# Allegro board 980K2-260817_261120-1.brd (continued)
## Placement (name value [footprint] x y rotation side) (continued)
NOREF#2378  -  []  268.19 247.71 0 top
NOREF#2379  -  []  216.55 194.49 90 top
NOREF#2380  -  []  138.35 209.04 0 top
NOREF#2381  -  []  260.95 261.55 90 top
NOREF#2382  -  []  277.71 233.69 90 top
NOREF#2383  -  []  269.67 250.01 0 top
NOREF#2384  -  []  248.42 205.58 0 top
NOREF#2385  -  []  136.55 254.49 90 top
NOREF#2386  -  []  268.78 244.35 0 top
NOREF#2387  -  []  192.72 257.6 0 top
NOREF#2388  -  []  220.83 203.76 90 top
NOREF#2389  -  []  148.19 187.71 0 top
NOREF#2390  -  []  232.11 231.4 0 top
NOREF#2391  -  []  118.64 291.4 0 top
NOREF#2392  -  []  176.26 203.76 90 top
NOREF#2393  -  []  196.1 220.99 90 top
NOREF#2394  -  []  228.99 180.62 0 top
NOREF#2395  -  []  122.44 232.28 0 top
NOREF#2396  -  []  230.6 233.69 0 top
NOREF#2397  -  []  155.05 274.25 0 top
NOREF#2398  -  []  265.42 214.72 90 top
NOREF#2399  -  []  252.55 284.49 0 top
NOREF#2400  -  []  188.78 222.65 0 top
NOREF#2401  -  []  197.03 178.07 0 top
NOREF#2402  -  []  203.97 265.9 0 top
NOREF#2403  -  []  191.46 167 0 top
NOREF#2404  -  []  244.95 270.32 90 top
NOREF#2405  -  []  124.44 292.28 90 top
NOREF#2406  -  []  153.18 184.35 0 top
NOREF#2407  -  []  192.25 278.02 90 top
NOREF#2408  -  []  181.03 267.69 90 top
NOREF#2409  -  []  243.97 214.54 0 top
NOREF#2410  -  []  249.52 200.42 90 top
NOREF#2411  -  []  139.72 213.6 90 top
NOREF#2412  -  []  232.63 233.69 90 top
NOREF#2413  -  []  266.43 282.49 90 top
NOREF#2414  -  []  150.21 82.65 0 top
NOREF#2415  -  []  191.98 220.75 90 top
NOREF#2416  -  []  193.18 184.35 0 top
NOREF#2417  -  []  217.25 176.5 90 top
NOREF#2418  -  []  235.92 250.88 90 top
NOREF#2419  -  []  276.1 271.85 90 top
NOREF#2420  -  []  276.57 185.63 90 top
NOREF#2421  -  []  152.13 220.09 0 top
NOREF#2422  -  []  159.27 211.67 0 top
NOREF#2423  -  []  210.89 209.17 0 top
NOREF#2424  -  []  275.49 228.7 90 top
NOREF#2425  -  []  147.77 252.5 0 top
NOREF#2426  -  []  246.32 209.17 0 top
NOREF#2427  -  []  191.46 227 0 top
NOREF#2428  -  []  286.32 202.32 0 top
NOREF#2429  -  []  148.32 245.63 90 top
NOREF#2430  -  []  143.36 258.18 0 top
NOREF#2431  -  []  279.4 214.54 0 top
NOREF#2432  -  []  176.55 220.49 0 top
NOREF#2433  -  []  237.25 196.75 0 top
NOREF#2434  -  []  199.22 239.57 90 top
NOREF#2435  -  []  321.52 456.29 0 top
NOREF#2436  -  []  271.19 278.07 0 top
NOREF#2437  -  []  281.75 266.13 0 top
NOREF#2438  -  []  273.56 233.37 90 top
NOREF#2439  -  []  163.84 273.41 90 top
NOREF#2440  -  []  190.73 19.69 90 top
NOREF#2441  -  []  222.87 273.02 0 top
NOREF#2442  -  []  227.77 241.47 0 top
NOREF#2443  -  []  251.25 244.35 0 top
NOREF#2444  -  []  202.26 176.17 90 top
NOREF#2445  -  []  275.96 228.6 90 top
NOREF#2446  -  []  236.8 274.65 90 top
NOREF#2447  -  []  197.25 196.75 0 top
NOREF#2448  -  []  272.11 231.4 0 top
NOREF#2449  -  []  170.92 291.95 90 top
NOREF#2450  -  []  196.54 227 0 top
NOREF#2451  -  []  208.54 207.5 90 top
NOREF#2452  -  []  131.22 234.24 90 top
NOREF#2453  -  []  176.55 254.49 90 top
NOREF#2454  -  []  262.87 226.99 0 top
NOREF#2455  -  []  271.95 178.07 0 top
NOREF#2456  -  []  203.97 208.95 0 top
NOREF#2457  -  []  138.97 271.91 90 top
NOREF#2458  -  []  211.25 244.35 0 top
NOREF#2459  -  []  255.02 268.14 90 top
NOREF#2460  -  []  203.97 272 0 top
NOREF#2461  -  []  163.97 208.95 0 top
NOREF#2462  -  []  236.02 192.78 0 top
NOREF#2463  -  []  267.3 286.19 0 top
NOREF#2464  -  []  162.2 178.35 0 top
NOREF#2465  -  []  253.36 201.22 0 top
NOREF#2466  -  []  159.4 205.9 0 top
NOREF#2467  -  []  148.44 193.03 90 top
NOREF#2468  -  []  181.55 269.94 90 top
NOREF#2469  -  []  181.6 294.14 0 top
NOREF#2470  -  []  230.56 197.6 0 top
NOREF#2471  -  []  272.63 232.86 0 top
NOREF#2472  -  []  175.65 244.35 0 top
NOREF#2473  -  []  228.99 251.93 0 top
NOREF#2474  -  []  180.95 261.55 90 top
NOREF#2475  -  []  232.66 166.36 90 top
NOREF#2476  -  []  109.54 14.59 90 top
NOREF#2477  -  []  168.45 235.2 0 top
NOREF#2478  -  []  279.4 274.54 0 top
NOREF#2479  -  []  154.86 454.29 90 top
NOREF#2480  -  []  151.11 253.35 0 top
NOREF#2481  -  []  253.45 184.35 0 top
NOREF#2482  -  []  193.39 197.85 90 top
NOREF#2483  -  []  163.84 214.21 0 top
NOREF#2484  -  []  193.83 172.21 90 top
NOREF#2485  -  []  239.72 219.22 90 top
NOREF#2486  -  []  259.55 294.49 0 top
NOREF#2487  -  []  228.32 198.18 0 top
NOREF#2488  -  []  189.12 256.43 90 top
NOREF#2489  -  []  134.38 264.09 0 top
NOREF#2490  -  []  133.95 281.02 90 top
NOREF#2491  -  []  180.95 208.91 90 top
NOREF#2492  -  []  178.97 18.69 90 top
NOREF#2493  -  []  187.99 178.35 0 top
NOREF#2494  -  []  196.57 185.63 0 top
NOREF#2495  -  []  246.32 266.13 0 top
NOREF#2496  -  []  205.38 226.23 0 top
NOREF#2497  -  []  186.83 256.75 0 top
NOREF#2498  -  []  153.83 172.21 90 top
NOREF#2499  -  []  89.76 165.64 0 top
NOREF#2500  -  []  273.76 255.7 90 top
NOREF#2501  -  []  196.52 285.69 0 top
NOREF#2502  -  []  275.15 236.17 90 top
NOREF#2503  -  []  269.55 188.99 90 top
NOREF#2504  -  []  195.17 281.32 0 top
NOREF#2505  -  []  271.79 196.75 0 top
NOREF#2506  -  []  171.65 293.3 90 top
NOREF#2507  -  []  195.05 214.25 0 top
NOREF#2508  -  []  290.89 262.32 0 top
NOREF#2509  -  []  235.92 190.88 90 top
NOREF#2510  -  []  250.89 266.13 0 top
NOREF#2511  -  []  156.8 220.49 90 top
NOREF#2512  -  []  163.84 270.87 90 top
NOREF#2513  -  []  256.98 205.11 90 top
NOREF#2514  -  []  139.08 203.76 0 top
NOREF#2515  -  []  192.13 224.66 0 top
NOREF#2516  -  []  210.89 269.17 0 top
NOREF#2517  -  []  236.61 233.37 90 top
NOREF#2518  -  []  149.12 196.43 90 top
NOREF#2519  -  []  133.68 389.27 90 top
NOREF#2520  -  []  258.95 261.55 0 top
NOREF#2521  -  []  251.21 294.89 90 top
NOREF#2522  -  []  151.91 196.43 90 top
NOREF#2523  -  []  132.26 248.4 0 top
NOREF#2524  -  []  229.84 213.7 0 top
NOREF#2525  -  []  282.26 236.17 90 top
NOREF#2526  -  []  231.71 171.3 0 top
NOREF#2527  -  []  182.81 257.6 0 top
NOREF#2528  -  []  218.35 211.84 0 top
NOREF#2529  -  []  225.61 257.6 0 top
NOREF#2530  -  []  220.43 284.38 90 top
NOREF#2531  -  []  248.42 204.78 90 top
NOREF#2532  -  []  149.29 276.17 90 top
NOREF#2533  -  []  242.44 232.28 0 top
NOREF#2534  -  []  216.63 292.23 0 top
NOREF#2535  -  []  236.1 211.85 90 top
NOREF#2536  -  []  275.49 168.7 90 top
NOREF#2537  -  []  174.38 204.09 0 top
NOREF#2538  -  []  248.42 261.77 0 top
NOREF#2539  -  []  226.16 200.17 90 top
NOREF#2540  -  []  236.52 221.12 0 top
NOREF#2541  -  []  288.42 208.62 0 top
NOREF#2542  -  []  251.25 244.35 0 top
NOREF#2543  -  []  152.63 172.86 0 top
NOREF#2544  -  []  138.95 208.91 0 top
NOREF#2545  -  []  239.27 260.97 90 top
NOREF#2546  -  []  214.38 264.09 0 top
NOREF#2547  -  []  237.71 173.69 0 top
NOREF#2548  -  []  198.11 232.1 0 top
NOREF#2549  -  []  279.4 200.64 90 top
NOREF#2550  -  []  203.97 260.64 90 top
NOREF#2551  -  []  243.97 200.64 90 top
NOREF#2552  -  []  164.64 241.15 90 top
NOREF#2553  -  []  168.42 261.77 0 top
NOREF#2554  -  []  205.38 286.23 0 top
NOREF#2555  -  []  168.42 268.62 0 top
NOREF#2556  -  []  267.43 278.27 90 top
NOREF#2557  -  []  271.24 193.03 90 top
NOREF#2558  -  []  198.64 173.37 90 top
NOREF#2559  -  []  199.27 201.77 0 top
NOREF#2560  -  []  187.43 218.27 90 top
NOREF#2561  -  []  258.97 211.91 90 top
NOREF#2562  -  []  191.85 18.69 0 top
NOREF#2563  -  []  250.02 274.45 0 top
NOREF#2564  -  []  239.27 271.67 0 top
NOREF#2565  -  []  226.7 283.04 90 top
NOREF#2566  -  []  278.64 173.37 90 top
NOREF#2567  -  []  128.94 265.53 0 top
NOREF#2568  -  []  156.52 216.55 0 top
NOREF#2569  -  []  269.12 240.3 90 top
NOREF#2570  -  []  146.01 195.7 90 top
NOREF#2571  -  []  265.41 213.02 90 top
NOREF#2572  -  []  260.95 204.09 90 top
NOREF#2573  -  []  199.4 208.95 0 top
NOREF#2574  -  []  286.32 206.13 0 top
NOREF#2575  -  []  106.83 148.19 90 top
NOREF#2576  -  []  283.84 264.78 90 top
NOREF#2577  -  []  163.84 264.78 90 top
NOREF#2578  -  []  248.94 221.73 0 top
NOREF#2579  -  []  276.57 185.63 0 top
NOREF#2580  -  []  214.38 204.09 0 top
NOREF#2581  -  []  188.44 193.03 90 top
NOREF#2582  -  []  244.44 292.28 90 top
NOREF#2583  -  []  267.77 241.47 0 top
NOREF#2584  -  []  263.49 193.03 90 top
NOREF#2585  -  []  191.73 232.54 0 top
NOREF#2586  -  []  271.73 232.54 0 top
NOREF#2587  -  []  196.1 271.85 90 top
NOREF#2588  -  []  151.76 227.33 0 top
NOREF#2589  -  []  163.97 200.64 90 top
NOREF#2590  -  []  125.04 233.3 90 top
NOREF#2591  -  []  119.46 18.69 90 top
NOREF#2592  -  []  226.96 251.6 90 top
NOREF#2593  -  []  279.72 274.65 90 top
NOREF#2594  -  []  219.55 294.49 0 top
NOREF#2595  -  []  199.27 214.21 0 top
NOREF#2596  -  []  199.65 272.56 0 top
NOREF#2597  -  []  229.84 284.11 90 top
NOREF#2598  -  []  276.8 214.65 90 top
NOREF#2599  -  []  149.84 273.7 0 top
NOREF#2600  -  []  191.98 280.75 90 top
NOREF#2601  -  []  135.24 201.55 90 top
NOREF#2602  -  []  252.64 204.47 0 top
NOREF#2603  -  []  263.36 253.35 0 top
NOREF#2604  -  []  226.83 191.93 0 top
NOREF#2605  -  []  243.84 200.97 90 top
NOREF#2606  -  []  226.16 260.17 90 top
NOREF#2607  -  []  196.8 285.06 90 top
NOREF#2608  -  []  224.04 256.75 0 top
NOREF#2609  -  []  193.95 256.75 0 top
NOREF#2610  -  []  147.03 171.4 0 top
NOREF#2611  -  []  136.5 285.91 90 top
NOREF#2612  -  []  243.97 265.9 0 top
NOREF#2613  -  []  180.95 268.91 90 top
NOREF#2614  -  []  201.75 212.22 0 top
NOREF#2615  -  []  191.91 191.6 90 top
NOREF#2616  -  []  267.43 224.11 90 top
NOREF#2617  -  []  276.57 258.18 0 top
NOREF#2618  -  []  199.72 283.79 90 top
NOREF#2619  -  []  142.88 286.99 0 top
NOREF#2620  -  []  283.84 205.58 0 top
NOREF#2621  -  []  145.61 192.78 0 top
NOREF#2622  -  []  234.78 236.5 90 top
NOREF#2623  -  []  223.49 247.06 90 top
NOREF#2624  -  []  196.45 247.71 0 top
NOREF#2625  -  []  218.83 292.23 0 top
NOREF#2626  -  []  149.21 17.15 90 top
NOREF#2627  -  []  262.81 252.78 0 top
NOREF#2628  -  []  192.25 212.18 0 top
NOREF#2629  -  []  188.81 250.88 90 top
NOREF#2630  -  []  140.83 203.76 90 top
NOREF#2631  -  []  269.24 185.31 90 top
NOREF#2632  -  []  230.15 206.89 90 top
NOREF#2633  -  []  203.92 289.94 0 top
NOREF#2634  -  []  229.84 273.7 90 top
NOREF#2635  -  []  276.1 220.99 90 top
NOREF#2636  -  []  191.91 256.43 90 top
NOREF#2637  -  []  155.05 218.82 0 top
NOREF#2638  -  []  168.54 265.9 0 top
NOREF#2639  -  []  279.27 270.87 90 top
NOREF#2640  -  []  153.83 232.21 90 top
NOREF#2641  -  []  138.85 181.15 90 top
NOREF#2642  -  []  189.55 248.99 90 top
NOREF#2643  -  []  208.42 207.82 90 top
NOREF#2644  -  []  277.04 184.35 0 top
NOREF#2645  -  []  249.52 260.42 90 top
NOREF#2646  -  []  151.11 200.17 90 top
NOREF#2647  -  []  187.45 209.24 0 top
NOREF#2648  -  []  147.9 265.84 90 top
NOREF#2649  -  []  232.13 284.66 0 top
NOREF#2650  -  []  223.49 193.03 90 top
NOREF#2651  -  []  136.5 271.94 0 top
NOREF#2652  -  []  193.03 232.1 0 top
NOREF#2653  -  []  183.49 247.06 90 top
NOREF#2654  -  []  276.8 285.06 90 top
NOREF#2655  -  []  275.68 173.69 90 top
NOREF#2656  -  []  273.94 196.75 0 top
NOREF#2657  -  []  199.27 210.87 90 top
NOREF#2658  -  []  284.95 210.32 90 top
NOREF#2659  -  []  266.01 184.91 90 top
NOREF#2660  -  []  243.92 289.94 0 top
NOREF#2661  -  []  154.39 222.02 90 top
NOREF#2662  -  []  197.5 185.31 90 top
NOREF#2663  -  []  148.35 217.95 90 top
NOREF#2664  -  []  259.08 263.76 0 top
NOREF#2665  -  []  220.83 201.22 90 top
NOREF#2666  -  []  142.81 252.5 0 top
NOREF#2667  -  []  197.37 196.43 90 top
NOREF#2668  -  []  169.52 270.32 90 top
NOREF#2669  -  []  269.86 17.15 0 top
NOREF#2670  -  []  220.83 263.76 90 top
NOREF#2671  -  []  242.2 238.35 0 top
NOREF#2672  -  []  272.63 172.86 0 top
NOREF#2673  -  []  191.87 396.29 0 top
NOREF#2674  -  []  248.54 265.9 0 top
NOREF#2675  -  []  226.43 236.47 90 top
NOREF#2676  -  []  203.84 270.87 90 top
NOREF#2677  -  []  221.85 232.5 0 top
NOREF#2678  -  []  187.03 171.4 0 top
NOREF#2679  -  []  244.61 294.24 90 top
NOREF#2680  -  []  229.12 191.6 90 top
NOREF#2681  -  []  275.05 283.39 0 top
NOREF#2682  -  []  220.43 224.38 90 top
NOREF#2683  -  []  237.71 232.86 0 top
NOREF#2684  -  []  208.42 204.78 90 top
NOREF#2685  -  []  235.92 255.7 90 top
NOREF#2686  -  []  266.28 197.85 90 top
NOREF#2687  -  []  246.32 212.22 0 top
NOREF#2688  -  []  234.78 176.5 90 top
NOREF#2689  -  []  199.24 184.35 0 top
NOREF#2690  -  []  181.22 76.69 90 top
NOREF#2691  -  []  198.64 233.37 90 top
NOREF#2692  -  []  267.8 269.99 0 top
NOREF#2693  -  []  244.95 272.86 90 top
NOREF#2694  -  []  169.52 267.27 90 top
NOREF#2695  -  []  133.4 281.8 90 top
NOREF#2696  -  []  157.37 240.3 90 top
NOREF#2697  -  []  215.02 268.14 90 top
NOREF#2698  -  []  196.8 280.49 90 top
NOREF#2699  -  []  264.16 185.63 90 top
NOREF#2700  -  []  275.17 276.75 90 top
NOREF#2701  -  []  163.97 268.95 0 top
NOREF#2702  -  []  211.25 184.35 0 top
NOREF#2703  -  []  281.75 272.22 0 top
NOREF#2704  -  []  243.97 208.95 0 top
NOREF#2705  -  []  179.55 234.49 0 top
NOREF#2706  -  []  213.65 179.15 0 top
NOREF#2707  -  []  281.75 269.17 0 top
NOREF#2708  -  []  152.13 280.09 0 top
NOREF#2709  -  []  132.55 250.49 90 top
NOREF#2710  -  []  270.97 255.7 90 top
NOREF#2711  -  []  226.16 286.14 90 top
NOREF#2712  -  []  157.71 233.69 0 top
NOREF#2713  -  []  267.3 226.19 0 top
NOREF#2714  -  []  204.95 212.86 90 top
NOREF#2715  -  []  271.71 231.3 0 top
NOREF#2716  -  []  267.8 209.99 0 top
NOREF#2717  -  []  269.84 219.54 90 top
NOREF#2718  -  []  213.75 452.29 90 top
NOREF#2719  -  []  122.44 292.28 0 top
NOREF#2720  -  []  151.73 232.54 0 top
NOREF#2721  -  []  284.95 267.27 90 top
NOREF#2722  -  []  277.04 184.35 0 top
NOREF#2723  -  []  270.97 239.57 90 top
NOREF#2724  -  []  155.17 216.75 0 top
NOREF#2725  -  []  267.43 218.27 90 top
NOREF#2726  -  []  239.22 190.88 90 top
NOREF#2727  -  []  215.02 208.14 90 top
NOREF#2728  -  []  271.91 191.6 90 top
NOREF#2729  -  []  232.25 278.02 0 top
NOREF#2730  -  []  196.1 216.42 90 top
NOREF#2731  -  []  135.15 265.24 0 top
NOREF#2732  -  []  152.13 224.66 0 top
NOREF#2733  -  []  212.55 284.49 0 top
NOREF#2734  -  []  180.95 264.09 90 top
NOREF#2735  -  []  163.84 261.77 0 top
NOREF#2736  -  []  127.98 226.38 90 top
NOREF#2737  -  []  199.27 205.58 0 top
NOREF#2738  -  []  265.41 273.02 90 top
NOREF#2739  -  []  196.52 276.55 0 top
NOREF#2740  -  []  146.17 272.17 90 top
NOREF#2741  -  []  267.8 204.99 90 top
NOREF#2742  -  []  143.61 456.29 0 top
NOREF#2743  -  []  268.99 240.62 0 top
NOREF#2744  -  []  171.25 244.35 0 top
NOREF#2745  -  []  290.89 206.13 0 top
NOREF#2746  -  []  192.66 226.35 90 top
NOREF#2747  -  []  192.13 280.09 0 top
NOREF#2748  -  []  272.25 218.02 90 top
NOREF#2749  -  []  275.05 223.39 0 top
NOREF#2750  -  []  245.38 286.23 0 top
NOREF#2751  -  []  166.32 206.13 0 top
NOREF#2752  -  []  253.45 244.35 0 top
NOREF#2753  -  []  259.08 208.59 0 top
NOREF#2754  -  []  186.16 258.18 0 top
NOREF#2755  -  []  170.89 202.32 0 top
NOREF#2756  -  []  253.36 261.22 0 top
NOREF#2757  -  []  149.55 156.49 90 top
NOREF#2758  -  []  136.26 203.76 90 top
NOREF#2759  -  []  159.27 267.82 90 top
NOREF#2760  -  []  186.16 200.17 90 top
NOREF#2761  -  []  192.25 282.59 0 top
NOREF#2762  -  []  205.04 233.3 90 top
NOREF#2763  -  []  196.84 227.33 0 top
NOREF#2764  -  []  239.27 210.87 90 top
NOREF#2765  -  []  279.27 260.97 90 top
NOREF#2766  -  []  271.19 218.07 0 top
NOREF#2767  -  []  178.95 268.91 0 top
NOREF#2768  -  []  173.36 261.22 0 top
NOREF#2769  -  []  223.36 247.38 0 top
NOREF#2770  -  []  152.66 166.36 90 top
NOREF#2771  -  []  229.72 281.62 0 top
NOREF#2772  -  []  131.22 294.89 90 top
NOREF#2773  -  []  191.18 179.15 0 top
NOREF#2774  -  []  251.25 184.35 0 top
NOREF#2775  -  []  133.66 179.15 0 top
NOREF#2776  -  []  88.16 165.19 0 top
NOREF#2777  -  []  155.92 190.88 90 top
NOREF#2778  -  []  183.36 253.35 0 top
NOREF#2779  -  []  233.18 271.85 90 top
NOREF#2780  -  []  86.61 153.16 0 top
NOREF#2781  -  []  269.84 284.11 0 top
NOREF#2782  -  []  278.91 172.21 90 top
NOREF#2783  -  []  174.09 267.27 90 top
NOREF#2784  -  []  179.55 180.49 90 top
NOREF#2785  -  []  159.27 265.58 0 top
NOREF#2786  -  []  195.92 255.7 90 top
NOREF#2787  -  []  230.48 175.77 0 top
NOREF#2788  -  []  277.74 166.36 90 top
NOREF#2789  -  []  276.38 181.15 90 top
NOREF#2790  -  []  231.76 227.33 0 top
NOREF#2791  -  []  163.84 201.77 0 top
NOREF#2792  -  []  224.16 245.63 90 top
NOREF#2793  -  []  241.12 248.11 90 top
NOREF#2794  -  []  213.65 239.15 0 top
NOREF#2795  -  []  139.55 234.49 0 top
NOREF#2796  -  []  200.23 176.17 90 top
NOREF#2797  -  []  170.89 209.17 0 top
NOREF#2798  -  []  234.39 216.17 90 top
NOREF#2799  -  []  155.17 272.17 0 top
NOREF#2800  -  []  151.95 238.07 0 top
NOREF#2801  -  []  260.83 205.79 90 top
NOREF#2802  -  []  253.78 207.01 0 top
NOREF#2803  -  []  227.8 204.99 90 top
NOREF#2804  -  []  226.96 256.43 90 top
NOREF#2805  -  []  201.12 188.11 90 top
NOREF#2806  -  []  258.95 268.91 0 top
NOREF#2807  -  []  182.81 252.78 0 top
NOREF#2808  -  []  165.04 233.3 90 top
NOREF#2809  -  []  235.68 173.69 0 top
NOREF#2810  -  []  209.52 270.32 90 top
NOREF#2811  -  []  138.35 204.47 0 top
NOREF#2812  -  []  156.02 236.37 0 top
NOREF#2813  -  []  197.74 226.35 90 top
NOREF#2814  -  []  230.56 252.78 0 top
NOREF#2815  -  []  269.72 221.62 0 top
NOREF#2816  -  []  278.11 172.1 0 top
NOREF#2817  -  []  221.59 308.11 0 top
NOREF#2818  -  []  167.98 286.38 90 top
NOREF#2819  -  []  279.4 207.5 90 top
NOREF#2820  -  []  227.45 209.24 0 top
NOREF#2821  -  []  227.3 280.35 0 top
NOREF#2822  -  []  151.91 251.6 90 top
NOREF#2823  -  []  209.55 237.49 90 top
NOREF#2824  -  []  279.4 273.09 90 top
NOREF#2825  -  []  307.66 457.2 0 top
NOREF#2826  -  []  251.05 289.49 0 top
NOREF#2827  -  []  152.25 278.02 90 top
NOREF#2828  -  []  203.97 273.09 90 top
NOREF#2829  -  []  183.36 187.38 0 top
NOREF#2830  -  []  184.16 256.43 90 top
NOREF#2831  -  []  208.42 200.97 90 top
NOREF#2832  -  []  152.72 197.6 0 top
NOREF#2833  -  []  276.52 276.55 0 top
NOREF#2834  -  []  85.59 155.57 90 top
NOREF#2835  -  []  228.32 185.63 0 top
NOREF#2836  -  []  124.32 231.95 90 top
NOREF#2837  -  []  181.55 205.11 90 top
NOREF#2838  -  []  156.81 172.54 0 top
NOREF#2839  -  []  208.42 201.77 0 top
NOREF#2840  -  []  227.03 171.4 0 top
NOREF#2841  -  []  267.99 178.35 0 top
NOREF#2842  -  []  213.62 229.09 90 top
NOREF#2843  -  []  236.33 227.9 90 top
NOREF#2844  -  []  224.04 196.75 0 top
NOREF#2845  -  []  199.27 273.41 90 top
NOREF#2846  -  []  212.87 287.4 90 top
NOREF#2847  -  []  216.26 263.76 90 top
NOREF#2848  -  []  258.35 207.01 0 top
NOREF#2849  -  []  157.92 252.5 90 top
NOREF#2850  -  []  216.63 232.23 0 top
NOREF#2851  -  []  132.87 287.4 90 top
NOREF#2852  -  []  245.73 17.15 0 top
NOREF#2853  -  []  188.44 181.72 90 top
NOREF#2854  -  []  161.75 214.76 0 top
NOREF#2855  -  []  148.35 223.79 90 top
NOREF#2856  -  []  219.08 261.22 0 top
NOREF#2857  -  []  270.48 235.77 0 top
NOREF#2858  -  []  138.35 211.84 0 top
NOREF#2859  -  []  275.92 195.7 90 top
NOREF#2860  -  []  147.99 178.35 0 top
NOREF#2861  -  []  203.84 261.77 0 top
NOREF#2862  -  []  154.51 259.27 90 top
NOREF#2863  -  []  207.98 286.38 90 top
NOREF#2864  -  []  123.92 229.94 0 top
NOREF#2865  -  []  271.19 283.92 0 top
NOREF#2866  -  []  288.54 262.09 0 top
NOREF#2867  -  []  231.98 226.59 90 top
NOREF#2868  -  []  262.87 286.99 0 top
NOREF#2869  -  []  227.99 178.35 0 top
NOREF#2870  -  []  248.54 202.09 0 top
NOREF#2871  -  []  227.99 238.35 0 top
NOREF#2872  -  []  159.27 271.67 0 top
NOREF#2873  -  []  254.07 270.89 90 top
NOREF#2874  -  []  287.25 19.69 90 top
NOREF#2875  -  []  273.18 222.26 90 top
NOREF#2876  -  []  267.8 264.99 90 top
NOREF#2877  -  []  212.55 250.49 90 top
NOREF#2878  -  []  226.28 253.03 90 top
NOREF#2879  -  []  157.71 173.69 90 top
NOREF#2880  -  []  236.1 280.99 90 top
NOREF#2881  -  []  191.79 191.93 0 top
NOREF#2882  -  []  261.55 265.11 90 top
NOREF#2883  -  []  243.97 267.5 90 top
NOREF#2884  -  []  235.17 272.17 90 top
NOREF#2885  -  []  230.77 273.37 90 top
NOREF#2886  -  []  256.63 292.23 0 top
NOREF#2887  -  []  267.43 284.11 0 top
NOREF#2888  -  []  288.39 456.29 0 top
NOREF#2889  -  []  260.59 184.98 90 top
NOREF#2890  -  []  269.12 256.43 90 top
NOREF#2891  -  []  193.98 178.07 0 top
NOREF#2892  -  []  203.97 262.09 0 top
NOREF#2893  -  []  267.43 278.27 0 top
NOREF#2894  -  []  142.81 192.78 0 top
NOREF#2895  -  []  239.06 178.07 0 top
NOREF#2896  -  []  251.21 294.24 90 top
NOREF#2897  -  []  169.52 204.23 90 top
NOREF#2898  -  []  283.84 204.78 90 top
NOREF#2899  -  []  136.55 220.49 0 top
NOREF#2900  -  []  159.4 208.95 0 top
NOREF#2901  -  []  244.95 212.86 90 top
NOREF#2902  -  []  228.78 184.35 0 top
NOREF#2903  -  []  158.64 173.37 90 top
NOREF#2904  -  []  211.21 234.24 90 top
NOREF#2905  -  []  181.6 248.12 0 top
NOREF#2906  -  []  302.59 389.27 90 top
NOREF#2907  -  []  175.84 262.57 90 top
NOREF#2908  -  []  145.09 257.49 90 top
NOREF#2909  -  []  278.13 389.27 90 top
NOREF#2910  -  []  134.51 203.76 0 top
NOREF#2911  -  []  220.95 268.91 90 top
NOREF#2912  -  []  262.81 246.81 0 top
NOREF#2913  -  []  154.07 191.6 90 top
NOREF#2914  -  []  236.54 167 0 top
NOREF#2915  -  []  221.55 262.57 90 top
NOREF#2916  -  []  168.42 267.82 90 top
NOREF#2917  -  []  83.04 164.54 90 top
NOREF#2918  -  []  169.49 220.89 0 top
NOREF#2919  -  []  170.92 231.95 90 top
NOREF#2920  -  []  227.9 265.84 90 top
NOREF#2921  -  []  133.24 201.55 0 top
NOREF#2922  -  []  265.42 274.72 90 top
NOREF#2923  -  []  192.25 222.59 0 top
NOREF#2924  -  []  228.95 206.89 0 top
NOREF#2925  -  []  269.72 286.19 0 top
NOREF#2926  -  []  270.6 233.69 0 top
NOREF#2927  -  []  209.55 237.49 90 top
NOREF#2928  -  []  221.6 17.15 90 top
NOREF#2929  -  []  268.32 242.05 0 top
NOREF#2930  -  []  195.92 250.88 90 top
NOREF#2931  -  []  154.63 277.85 0 top
NOREF#2932  -  []  195.49 228.7 90 top
NOREF#2933  -  []  184.16 251.6 90 top
NOREF#2934  -  []  229.84 219.54 0 top
NOREF#2935  -  []  273.6 282.39 0 top
NOREF#2936  -  []  264.04 245.96 0 top
NOREF#2937  -  []  199.27 270.87 90 top
NOREF#2938  -  []  178.35 264.47 0 top
NOREF#2939  -  []  235.17 216.75 0 top
NOREF#2940  -  []  266.96 251.6 90 top
NOREF#2941  -  []  196.57 242.05 0 top
NOREF#2942  -  []  137.25 176.5 90 top
NOREF#2943  -  []  231.19 288.49 0 top
NOREF#2944  -  []  181.85 246.47 0 top
NOREF#2945  -  []  146.16 258.18 0 top
NOREF#2946  -  []  279.72 279.22 90 top
NOREF#2947  -  []  159.27 274.21 0 top
NOREF#2948  -  []  236.79 171.3 0 top
NOREF#2949  -  []  237.92 190.01 0 top
NOREF#2950  -  []  245.38 286.23 0 top
NOREF#2951  -  []  231.95 178.07 0 top
NOREF#2952  -  []  233.39 253.03 90 top
NOREF#2953  -  []  187.77 241.47 0 top
NOREF#2954  -  []  195.49 168.7 90 top
NOREF#2955  -  []  279.4 264.45 90 top
NOREF#2956  -  []  231.11 193.35 0 top
NOREF#2957  -  []  154.33 207.37 90 top
NOREF#2958  -  []  318.12 17.15 90 top
NOREF#2959  -  []  216.55 254.49 90 top
NOREF#2960  -  []  231.79 191.93 0 top
NOREF#2961  -  []  248.54 267.5 90 top
NOREF#2962  -  []  277.04 244.35 0 top
NOREF#2963  -  []  288.54 204.45 90 top
NOREF#2964  -  []  207.98 226.38 90 top
NOREF#2965  -  []  212.55 224.49 0 top
NOREF#2966  -  []  236.57 245.63 90 top
NOREF#2967  -  []  144.16 251.6 90 top
NOREF#2968  -  []  226.01 250.88 90 top
NOREF#2969  -  []  174.51 263.76 0 top
NOREF#2970  -  []  159.27 260.97 90 top
NOREF#2971  -  []  276.02 257.6 0 top
NOREF#2972  -  []  275.17 221.32 0 top
NOREF#2973  -  []  222.87 213.02 0 top
NOREF#2974  -  []  264.04 256.75 0 top
NOREF#2975  -  []  209.55 237.49 90 top
NOREF#2976  -  []  229.24 185.31 90 top
NOREF#2977  -  []  259.73 178.35 0 top
NOREF#2978  -  []  229.72 286.19 0 top
NOREF#2979  -  []  183.36 198.18 0 top
NOREF#2980  -  []  148.99 191.93 0 top
NOREF#2981  -  []  159.4 214.54 0 top
NOREF#2982  -  []  132.55 284.49 0 top
NOREF#2983  -  []  184.04 245.96 0 top
NOREF#2984  -  []  263.49 247.06 90 top
NOREF#2985  -  []  239.22 239.57 90 top
NOREF#2986  -  []  174.07 270.89 90 top
NOREF#2987  -  []  188.35 223.79 90 top
NOREF#2988  -  []  272.13 280.09 0 top
NOREF#2989  -  []  235.05 223.39 0 top
NOREF#2990  -  []  270.86 82.65 0 top
NOREF#2991  -  []  197.74 166.36 90 top
NOREF#2992  -  []  125.25 291.4 0 top
NOREF#2993  -  []  209.87 389.27 90 top
NOREF#2994  -  []  169.05 232.28 0 top
NOREF#2995  -  []  165.49 452.29 90 top
NOREF#2996  -  []  149.67 252.5 90 top
NOREF#2997  -  []  239.27 261.77 0 top
NOREF#2998  -  []  233.39 197.85 90 top
NOREF#2999  -  []  264.24 18.69 0 top
NOREF#3000  -  []  179.08 261.22 0 top
NOREF#3001  -  []  141.85 246.47 0 top
NOREF#3002  -  []  203.84 213.41 90 top
NOREF#3003  -  []  289.52 204.23 90 top
NOREF#3004  -  []  260.83 268.59 90 top
NOREF#3005  -  []  235.05 214.25 0 top
NOREF#3006  -  []  275.17 212.18 90 top
NOREF#3007  -  []  208.42 268.62 0 top
NOREF#3008  -  []  130.52 295.42 90 top
NOREF#3009  -  []  162.2 238.35 0 top
NOREF#3010  -  []  288.39 456.29 90 top
NOREF#3011  -  []  195.17 221.32 90 top
NOREF#3012  -  []  277.25 191.93 0 top
NOREF#3013  -  []  250.92 291.95 90 top
NOREF#3014  -  []  279.4 202.09 0 top
NOREF#3015  -  []  146.17 286.14 90 top
NOREF#3016  -  []  196.02 252.78 0 top
NOREF#3017  -  []  148.32 245.63 0 top
NOREF#3018  -  []  248.42 200.97 90 top
NOREF#3019  -  []  144.04 191.93 0 top
NOREF#3020  -  []  253.62 289.09 90 top
NOREF#3021  -  []  236.02 252.78 0 top
NOREF#3022  -  []  89.74 155.92 0 top
NOREF#3023  -  []  279.27 271.67 0 top
NOREF#3024  -  []  267.43 218.27 0 top
NOREF#3025  -  []  203.84 267.82 90 top
NOREF#3026  -  []  205.74 14.59 90 top
NOREF#3027  -  []  272.72 257.6 0 top
NOREF#3028  -  []  152.11 231.4 0 top
NOREF#3029  -  []  146.96 191.6 90 top
NOREF#3030  -  []  206.32 269.17 0 top
NOREF#3031  -  []  208.94 281.73 0 top
NOREF#3032  -  []  267.03 231.4 0 top
NOREF#3033  -  []  203.92 229.94 0 top
NOREF#3034  -  []  269.72 275.77 0 top
NOREF#3035  -  []  243.97 204.45 90 top
NOREF#3036  -  []  221.55 265.11 90 top
NOREF#3037  -  []  227.3 286.19 0 top
NOREF#3038  -  []  247.04 299.09 0 top
NOREF#3039  -  []  163.97 272 0 top
NOREF#3040  -  []  272.87 248.11 90 top
NOREF#3041  -  []  133.64 239.09 0 top
NOREF#3042  -  []  283.97 208.95 0 top
NOREF#3043  -  []  203.97 210.55 90 top
NOREF#3044  -  []  191.11 258.18 0 top
NOREF#3045  -  []  143.49 187.06 90 top
NOREF#3046  -  []  249.52 204.23 90 top
NOREF#3047  -  []  169.05 292.28 0 top
NOREF#3048  -  []  148.44 181.72 90 top
NOREF#3049  -  []  166.32 266.13 0 top
NOREF#3050  -  []  239.4 205.9 0 top
NOREF#3051  -  []  178.35 204.47 0 top
NOREF#3052  -  []  185.41 286.99 90 top
NOREF#3053  -  []  261.55 209.94 90 top
NOREF#3054  -  []  203.97 200.64 90 top
NOREF#3055  -  []  241.75 206.13 0 top
NOREF#3056  -  []  274.33 207.37 90 top
NOREF#3057  -  []  272.13 214.25 0 top
NOREF#3058  -  []  277.92 250.01 0 top
NOREF#3059  -  []  266.28 253.03 90 top
NOREF#3060  -  []  239.27 204.78 90 top
NOREF#3061  -  []  209.52 272.86 90 top
NOREF#3062  -  []  244.95 267.27 90 top
NOREF#3063  -  []  272.25 272.17 0 top
NOREF#3064  -  []  229.67 190.01 0 top
NOREF#3065  -  []  216.26 203.76 90 top
NOREF#3066  -  []  148.78 184.35 0 top
NOREF#3067  -  []  211.14 458.49 0 top
NOREF#3068  -  []  267.43 224.11 0 top
NOREF#3069  -  []  151.11 198.18 0 top
NOREF#3070  -  []  237.25 180.62 0 top
NOREF#3071  -  []  140.95 201.55 90 top
NOREF#3072  -  []  208.54 208.95 0 top
NOREF#3073  -  []  187.77 181.47 0 top
NOREF#3074  -  []  174.43 292.23 0 top
NOREF#3075  -  []  197.37 180.3 90 top
NOREF#3076  -  []  155.68 173.69 0 top
NOREF#3077  -  []  203.97 268.95 0 top
NOREF#3078  -  []  153.18 211.85 90 top
NOREF#3079  -  []  273.39 253.03 90 top
NOREF#3080  -  []  183.49 193.03 90 top
NOREF#3081  -  []  137.28 286.47 0 top
NOREF#3082  -  []  172.55 284.49 0 top
NOREF#3083  -  []  224.16 251.6 90 top
NOREF#3084  -  []  131.26 184.35 0 top
NOREF#3085  -  []  131.05 245.49 90 top
NOREF#3086  -  []  193.18 211.85 90 top
NOREF#3087  -  []  227.77 192.78 0 top
NOREF#3088  -  []  150.56 197.6 0 top
NOREF#3089  -  []  173.24 201.55 0 top
NOREF#3090  -  []  236.38 241.15 90 top
NOREF#3091  -  []  173.62 229.09 90 top
NOREF#3092  -  []  265.09 197.49 90 top
NOREF#3093  -  []  236.57 253.35 0 top
NOREF#3094  -  []  213.36 261.22 0 top
NOREF#3095  -  []  264.04 251.93 0 top
NOREF#3096  -  []  248.42 201.77 0 top
NOREF#3097  -  []  260.83 208.59 90 top
NOREF#3098  -  []  146.83 196.75 0 top
NOREF#3099  -  []  276.33 227.9 90 top
NOREF#3100  -  []  228.78 228.49 0 top
NOREF#3101  -  []  184.16 245.63 90 top
NOREF#3102  -  []  279.22 255.7 90 top
NOREF#3103  -  []  271.79 256.75 0 top
NOREF#3104  -  []  243.84 207.82 90 top
NOREF#3105  -  []  235.05 218.82 0 top
NOREF#3106  -  []  270.77 283.79 90 top
NOREF#3107  -  []  288.54 205.9 0 top
NOREF#3108  -  []  226.83 196.75 0 top
NOREF#3109  -  []  188.78 228.49 0 top
NOREF#3110  -  []  271.11 258.18 0 top
NOREF#3111  -  []  169.17 291.95 0 top
NOREF#3112  -  []  144.16 245.63 90 top
NOREF#3113  -  []  264.04 185.96 0 top
NOREF#3114  -  []  149.68 334.65 0 top
NOREF#3115  -  []  188.32 245.63 90 top
NOREF#3116  -  []  187.3 220.35 0 top
NOREF#3117  -  []  218.35 267.01 0 top
NOREF#3118  -  []  153.6 222.39 0 top
NOREF#3119  -  []  231.24 197.85 90 top
NOREF#3120  -  []  192.11 171.4 0 top
NOREF#3121  -  []  210.92 291.95 90 top
NOREF#3122  -  []  220.59 184.98 90 top
NOREF#3123  -  []  228.32 253.35 0 top
NOREF#3124  -  []  213.24 261.55 0 top
NOREF#3125  -  []  258.35 269.04 0 top
NOREF#3126  -  []  251.05 229.49 0 top
NOREF#3127  -  []  230.56 257.6 0 top
NOREF#3128  -  []  230.97 239.57 90 top
NOREF#3129  -  []  204.64 181.15 90 top
NOREF#3130  -  []  240.13 456.29 90 top
NOREF#3131  -  []  276.02 192.78 0 top
NOREF#3132  -  []  94.87 108.59 0 top
NOREF#3133  -  []  163.84 210.87 90 top
NOREF#3134  -  []  266.69 223.05 90 top
NOREF#3135  -  []  218.95 204.09 0 top
NOREF#3136  -  []  202.44 292.28 0 top
NOREF#3137  -  []  233.76 255.7 90 top
NOREF#3138  -  []  196.61 173.37 90 top
NOREF#3139  -  []  156.02 192.78 0 top
NOREF#3140  -  []  239.4 262.09 0 top
NOREF#3141  -  []  248.54 262.09 0 top
NOREF#3142  -  []  204.95 200.42 90 top
NOREF#3143  -  []  223.36 193.35 0 top
NOREF#3144  -  []  231.95 238.07 0 top
NOREF#3145  -  []  213.45 244.35 0 top
NOREF#3146  -  []  277.5 185.31 90 top
NOREF#3147  -  []  246.32 262.32 0 top
NOREF#3148  -  []  176.83 227.03 0 top
NOREF#3149  -  []  225.41 226.99 90 top
NOREF#3150  -  []  199.4 267.5 90 top
NOREF#3151  -  []  209.55 237.49 0 top
NOREF#3152  -  []  263.49 253.03 90 top
NOREF#3153  -  []  260.43 224.38 90 top
NOREF#3154  -  []  249.49 280.89 0 top
NOREF#3155  -  []  195.05 218.82 0 top
NOREF#3156  -  []  181.55 202.57 90 top
NOREF#3157  -  []  263.36 198.18 0 top
NOREF#3158  -  []  266.43 236.47 90 top
NOREF#3159  -  []  204.44 292.28 90 top
NOREF#3160  -  []  186.96 256.43 90 top
NOREF#3161  -  []  201.12 248.11 90 top
NOREF#3162  -  []  186.83 191.93 0 top
NOREF#3163  -  []  199.72 279.22 90 top
NOREF#3164  -  []  196.84 167.33 0 top
NOREF#3165  -  []  275.17 216.75 90 top
NOREF#3166  -  []  172.37 392.33 90 top
NOREF#3167  -  []  276.81 232.54 0 top
NOREF#3168  -  []  254.51 263.76 0 top
NOREF#3169  -  []  244.64 181.15 90 top
NOREF#3170  -  []  157.92 236.37 90 top
NOREF#3171  -  []  231.19 228.49 0 top
NOREF#3172  -  []  230.77 213.37 90 top
NOREF#3173  -  []  164.32 231.95 90 top
NOREF#3174  -  []  199.22 250.88 90 top
NOREF#3175  -  []  244.95 200.42 90 top
NOREF#3176  -  []  201.75 262.32 0 top
NOREF#3177  -  []  269.72 226.19 0 top
NOREF#3178  -  []  88.44 105.03 90 top
NOREF#3179  -  []  259.55 234.49 0 top
NOREF#3180  -  []  230.6 173.69 90 top
NOREF#3181  -  []  152.61 456.29 0 top
NOREF#3182  -  []  283.84 208.62 0 top
NOREF#3183  -  []  235.17 281.32 0 top
NOREF#3184  -  []  228.78 282.65 0 top
NOREF#3185  -  []  170.89 266.13 0 top
NOREF#3186  -  []  288.42 207.82 90 top
NOREF#3187  -  []  167.74 456.29 90 top
NOREF#3188  -  []  161.75 269.17 0 top
NOREF#3189  -  []  149.12 240.3 90 top
NOREF#3190  -  []  88.44 106.3 90 top
NOREF#3191  -  []  135.15 263.21 90 top
NOREF#3192  -  []  85.59 135.25 90 top
NOREF#3193  -  []  146.01 184.91 90 top
NOREF#3194  -  []  190.97 239.57 90 top
NOREF#3195  -  []  235.92 195.7 90 top
NOREF#3196  -  []  215.84 262.57 90 top
NOREF#3197  -  []  168.42 260.97 90 top
NOREF#3198  -  []  196.57 185.63 90 top
NOREF#3199  -  []  150.77 223.79 90 top
NOREF#3200  -  []  199.44 239.15 0 top
NOREF#3201  -  []  230.97 250.88 90 top
NOREF#3202  -  []  243.84 210.87 90 top
NOREF#3203  -  []  273.18 277.69 90 top
NOREF#3204  -  []  191.11 260.17 90 top
NOREF#3205  -  []  208.54 265.9 0 top
NOREF#3206  -  []  283.97 260.64 90 top
NOREF#3207  -  []  166.32 272.22 0 top
NOREF#3208  -  []  144.16 185.63 90 top
NOREF#3209  -  []  193.27 193.35 0 top
NOREF#3210  -  []  190.98 244.35 0 top
NOREF#3211  -  []  199.72 214.65 90 top
NOREF#3212  -  []  183.49 187.06 90 top
NOREF#3213  -  []  253.24 261.55 0 top
NOREF#3214  -  []  222.81 192.78 0 top
NOREF#3215  -  []  243.84 274.21 0 top
NOREF#3216  -  []  276.79 231.3 0 top
NOREF#3217  -  []  271.18 179.15 0 top
NOREF#3218  -  []  156.1 220.99 90 top
NOREF#3219  -  []  189.72 281.62 0 top
NOREF#3220  -  []  249.52 207.27 90 top
NOREF#3221  -  []  156.1 280.99 90 top
NOREF#3222  -  []  202.44 232.28 0 top
NOREF#3223  -  []  91.03 127.87 0 top
NOREF#3224  -  []  237.03 238.07 0 top
NOREF#3225  -  []  155.68 233.69 90 top
NOREF#3226  -  []  229.84 279.54 90 top
NOREF#3227  -  []  151.79 251.93 0 top
NOREF#3228  -  []  187.3 226.19 0 top
NOREF#3229  -  []  93.68 136.27 0 top
NOREF#3230  -  []  226.16 258.18 0 top
NOREF#3231  -  []  135.15 268.04 0 top
NOREF#3232  -  []  162.57 291.95 0 top
NOREF#3233  -  []  273.27 198.18 0 top
NOREF#3234  -  []  189.12 240.3 90 top
NOREF#3235  -  []  138.85 241.15 90 top
NOREF#3236  -  []  246.32 206.13 0 top
NOREF#3237  -  []  233.18 244.35 0 top
NOREF#3238  -  []  89.74 135.6 90 top
NOREF#3239  -  []  159.4 270.55 90 top
NOREF#3240  -  []  236.52 281.12 0 top
NOREF#3241  -  []  273.98 178.07 0 top
NOREF#3242  -  []  232.63 173.69 0 top
NOREF#3243  -  []  266.28 193.03 90 top
NOREF#3244  -  []  271.24 197.85 90 top
NOREF#3245  -  []  189.67 250.01 0 top
NOREF#3246  -  []  228.19 247.71 0 top
NOREF#3247  -  []  191.79 256.75 0 top
NOREF#3248  -  []  277.25 196.75 0 top
NOREF#3249  -  []  281.75 209.17 0 top
NOREF#3250  -  []  203.84 268.62 0 top
NOREF#3251  -  []  277.03 238.07 0 top
NOREF#3252  -  []  204.64 241.15 90 top
NOREF#3253  -  []  147.8 209.99 0 top
NOREF#3254  -  []  188.99 196.75 0 top
NOREF#3255  -  []  148.99 180.62 0 top
NOREF#3256  -  []  244.95 204.23 90 top
NOREF#3257  -  []  193.18 271.85 90 top
NOREF#3258  -  []  188.78 288.49 0 top
NOREF#3259  -  []  275.17 281.32 0 top
NOREF#3260  -  []  228.78 244.35 0 top
NOREF#3261  -  []  233.03 232.1 0 top
NOREF#3262  -  []  266.16 272.17 90 top
NOREF#3263  -  []  199.4 274.54 0 top
NOREF#3264  -  []  181.03 207.69 90 top
NOREF#3265  -  []  148.95 206.89 0 top
NOREF#3266  -  []  163.97 204.45 90 top
NOREF#3267  -  []  199.4 207.5 90 top
NOREF#3268  -  []  233.94 251.93 0 top
NOREF#3269  -  []  297.39 456.29 0 top
NOREF#3270  -  []  186.96 196.43 90 top
NOREF#3271  -  []  186.16 260.17 90 top
NOREF#3272  -  []  196.54 167 0 top
NOREF#3273  -  []  196.45 187.71 0 top
NOREF#3274  -  []  145.42 213.02 90 top
NOREF#3275  -  []  194.78 236.5 90 top
NOREF#3276  -  []  227.8 205.39 90 top
NOREF#3277  -  []  179.55 240.49 90 top
NOREF#3278  -  []  144.16 191.6 90 top
NOREF#3279  -  []  186.43 236.47 90 top
NOREF#3280  -  []  163.92 229.94 0 top
NOREF#3281  -  []  146.96 256.43 90 top
NOREF#3282  -  []  211.05 229.49 0 top
NOREF#3283  -  []  140.95 204.09 90 top
NOREF#3284  -  []  179.08 205.79 0 top
NOREF#3285  -  []  163.84 268.62 0 top
NOREF#3286  -  []  144.16 196.43 90 top
NOREF#3287  -  []  211.05 292.28 90 top
NOREF#3288  -  []  162.44 292.28 0 top
NOREF#3289  -  []  151.7 274.65 90 top
NOREF#3290  -  []  194.39 222.02 90 top
NOREF#3291  -  []  211.65 293.3 90 top
NOREF#3292  -  []  269.86 17.15 90 top
NOREF#3293  -  []  294.09 267.27 90 top
NOREF#3294  -  []  151.24 257.85 90 top
NOREF#3295  -  []  273.76 250.88 90 top
NOREF#3296  -  []  186.28 197.85 90 top
NOREF#3297  -  []  197.04 184.35 0 top
NOREF#3298  -  []  174.09 260.42 90 top
NOREF#3299  -  []  256.55 220.49 0 top
NOREF#3300  -  []  146.28 257.85 90 top
NOREF#3301  -  []  276.52 225.69 0 top
NOREF#3302  -  []  138.97 211.91 90 top
NOREF#3303  -  []  220.83 208.59 90 top
NOREF#3304  -  []  276.57 245.63 90 top
NOREF#3305  -  []  276.57 182.05 0 top
NOREF#3306  -  []  174.04 210.63 90 top
NOREF#3307  -  []  261.03 267.69 90 top
NOREF#3308  -  []  153.76 190.88 90 top
NOREF#3309  -  []  199.27 267.82 90 top
NOREF#3310  -  []  187.43 218.27 0 top
NOREF#3311  -  []  241.75 272.22 0 top
NOREF#3312  -  []  162.2 238.35 0 top
NOREF#3313  -  []  223.89 185.24 90 top
NOREF#3314  -  []  273.39 197.85 90 top
NOREF#3315  -  []  187.05 269.24 0 top
NOREF#3316  -  []  114.61 17.78 0 top
NOREF#3317  -  []  165.04 293.3 90 top
NOREF#3318  -  []  214.09 204.23 90 top
NOREF#3319  -  []  152.63 232.86 0 top
NOREF#3320  -  []  273.98 238.07 0 top
NOREF#3321  -  []  159.65 212.56 0 top
NOREF#3322  -  []  153.39 257.85 90 top
NOREF#3323  -  []  188.99 180.62 0 top
NOREF#3324  -  []  191.76 227.33 0 top
NOREF#3325  -  []  273.27 258.18 0 top
NOREF#3326  -  []  223.49 197.85 90 top
NOREF#3327  -  []  187.9 205.84 90 top
NOREF#3328  -  []  248.42 268.62 0 top
NOREF#3329  -  []  312.52 396.29 0 top
NOREF#3330  -  []  254.38 204.09 0 top
NOREF#3331  -  []  14.6 372.12 0 top
NOREF#3332  -  []  248.42 208.62 0 top
NOREF#3333  -  []  201.75 266.13 0 top
NOREF#3334  -  []  181.55 262.57 90 top
NOREF#3335  -  []  255.24 201.55 90 top
NOREF#3336  -  []  178.97 211.91 90 top
NOREF#3337  -  []  209.52 212.86 90 top
NOREF#3338  -  []  276.1 280.99 90 top
NOREF#3339  -  []  156.57 193.35 0 top
NOREF#3340  -  []  266.01 255.7 90 top
NOREF#3341  -  []  279.27 268.62 0 top
NOREF#3342  -  []  272.25 222.59 0 top
NOREF#3343  -  []  283.97 204.45 90 top
NOREF#3344  -  []  136.98 205.11 90 top
NOREF#3345  -  []  270.77 223.79 90 top
NOREF#3346  -  []  242.26 236.17 90 top
NOREF#3347  -  []  141.83 265.99 0 top
NOREF#3348  -  []  253.24 201.55 0 top
NOREF#3349  -  []  191.11 253.35 0 top
NOREF#3350  -  []  133.62 229.09 90 top
NOREF#3351  -  []  229.12 256.43 90 top
NOREF#3352  -  []  142.81 186.81 0 top
NOREF#3353  -  []  195.96 168.6 90 top
NOREF#3354  -  []  199.24 244.35 0 top
NOREF#3355  -  []  288.42 204.78 90 top
NOREF#3356  -  []  233.03 172.1 0 top
NOREF#3357  -  []  140.95 261.55 90 top
NOREF#3358  -  []  252.87 287.4 90 top
NOREF#3359  -  []  156.38 181.15 90 top
NOREF#3360  -  []  188.44 241.72 90 top
NOREF#3361  -  []  195.56 235.77 0 top
NOREF#3362  -  []  232.63 232.86 0 top
NOREF#3363  -  []  288.54 208.95 0 top
NOREF#3364  -  []  229.84 284.11 0 top
NOREF#3365  -  []  269.84 279.54 0 top
NOREF#3366  -  []  150.97 179.57 90 top
NOREF#3367  -  []  140.83 201.22 90 top
NOREF#3368  -  []  191.19 283.92 0 top
NOREF#3369  -  []  245.38 226.23 0 top
NOREF#3370  -  []  244.95 264.23 90 top
NOREF#3371  -  []  204.61 294.24 90 top
NOREF#3372  -  []  152.72 247.68 0 top
NOREF#3373  -  []  145.42 226.99 90 top
NOREF#3374  -  []  174.09 204.23 90 top
NOREF#3375  -  []  143.49 193.03 90 top
NOREF#3376  -  []  242.2 178.35 0 top
NOREF#3377  -  []  194.07 191.6 90 top
NOREF#3378  -  []  270.56 252.78 0 top
NOREF#3379  -  []  147.51 250.88 90 top
NOREF#3380  -  []  203.84 204.78 90 top
NOREF#3381  -  []  268.95 266.89 0 top
NOREF#3382  -  []  288.42 261.77 0 top
NOREF#3383  -  []  226.43 296.46 90 top
NOREF#3384  -  []  206.32 262.32 0 top
NOREF#3385  -  []  257.29 247.78 0 top
NOREF#3386  -  []  237.37 191.6 90 top
NOREF#3387  -  []  146.88 280.75 90 top
NOREF#3388  -  []  128.45 235.2 0 top
NOREF#3389  -  []  131.05 229.49 0 top
NOREF#3390  -  []  161.41 227.9 90 top
NOREF#3391  -  []  132.87 227.4 90 top
NOREF#3392  -  []  238.11 232.1 0 top
NOREF#3393  -  []  237.71 233.69 0 top
NOREF#3394  -  []  154.78 176.5 90 top
NOREF#3395  -  []  254.43 232.23 0 top
NOREF#3396  -  []  251.05 185.49 90 top
NOREF#3397  -  []  233.6 222.39 0 top
NOREF#3398  -  []  233.83 172.21 90 top
NOREF#3399  -  []  203.97 214.54 0 top
NOREF#3400  -  []  269.12 180.3 90 top
NOREF#3401  -  []  239.4 268.95 0 top
NOREF#3402  -  []  239.27 267.82 90 top
NOREF#3403  -  []  252.55 250.49 90 top
NOREF#3404  -  []  290.89 266.13 0 top
NOREF#3405  -  []  206.32 266.13 0 top
NOREF#3406  -  []  279.27 264.78 90 top
NOREF#3407  -  []  272.13 274.25 0 top
NOREF#3408  -  []  232.72 197.6 0 top
NOREF#3409  -  []  251.65 293.3 90 top
NOREF#3410  -  []  149.67 247.68 90 top
NOREF#3411  -  []  255.02 208.14 90 top
NOREF#3412  -  []  216.38 264.09 90 top
NOREF#3413  -  []  281.75 214.76 0 top
NOREF#3414  -  []  247.98 286.38 90 top
NOREF#3415  -  []  197.92 190.01 0 top
NOREF#3416  -  []  228.99 256.75 0 top
NOREF#3417  -  []  159.27 268.62 0 top
NOREF#3418  -  []  220.95 206.12 90 top
NOREF#3419  -  []  203.84 214.21 0 top
NOREF#3420  -  []  156.1 211.85 90 top
NOREF#3421  -  []  268.44 241.72 90 top
NOREF#3422  -  []  168.54 200.64 90 top
NOREF#3423  -  []  243.4 296.38 0 top
NOREF#3424  -  []  226.16 226.14 90 top
NOREF#3425  -  []  236.7 241.72 90 top
NOREF#3426  -  []  288.37 18.69 0 top
NOREF#3427  -  []  89.74 135.6 0 top
NOREF#3428  -  []  288.54 268.95 0 top
NOREF#3429  -  []  214.04 270.63 90 top
NOREF#3430  -  []  179.55 294.49 0 top
NOREF#3431  -  []  227.8 265.39 90 top
NOREF#3432  -  []  153.27 253.35 0 top
NOREF#3433  -  []  146.16 200.17 90 top
NOREF#3434  -  []  276.7 257.85 90 top
NOREF#3435  -  []  216.83 287.03 0 top
NOREF#3436  -  []  267.3 220.35 0 top
NOREF#3437  -  []  236.7 181.72 90 top
NOREF#3438  -  []  140.95 268.91 90 top
NOREF#3439  -  []  226.16 198.18 0 top
NOREF#3440  -  []  174.43 232.23 0 top
NOREF#3441  -  []  232.63 172.86 0 top
NOREF#3442  -  []  171.05 185.49 90 top
NOREF#3443  -  []  283.84 207.82 90 top
NOREF#3444  -  []  187.05 209.24 0 top
NOREF#3445  -  []  240.23 176.17 90 top
NOREF#3446  -  []  210.02 214.45 0 top
NOREF#3447  -  []  191.18 239.15 0 top
NOREF#3448  -  []  155.49 168.7 90 top
NOREF#3449  -  []  274.78 236.5 90 top
NOREF#3450  -  []  230.48 235.77 0 top
NOREF#3451  -  []  237.71 173.69 90 top
NOREF#3452  -  []  229.55 188.99 90 top
NOREF#3453  -  []  196.7 193.03 90 top
NOREF#3454  -  []  254.38 264.09 0 top
NOREF#3455  -  []  231.98 220.75 90 top
NOREF#3456  -  []  258.97 271.91 90 top
NOREF#3457  -  []  269.12 251.6 90 top
NOREF#3458  -  []  228.44 181.72 90 top
NOREF#3459  -  []  236.57 185.63 0 top
NOREF#3460  -  []  135.15 268.04 90 top
NOREF#3461  -  []  194.39 226.59 90 top
NOREF#3462  -  []  156.54 227 0 top
NOREF#3463  -  []  266.16 258.18 0 top
NOREF#3464  -  []  276.79 171.3 0 top
NOREF#3465  -  []  151.53 233.37 90 top
NOREF#3466  -  []  169.52 260.42 90 top
NOREF#3467  -  []  162.57 231.95 0 top
NOREF#3468  -  []  266.83 196.75 0 top
NOREF#3469  -  []  239.4 260.64 90 top
NOREF#3470  -  []  168.54 268.95 0 top
NOREF#3471  -  []  235.96 228.6 90 top
NOREF#3472  -  []  253.64 239.09 0 top
NOREF#3473  -  []  222.81 252.78 0 top
NOREF#3474  -  []  90.48 16.49 0 top
NOREF#3475  -  []  266.16 260.17 90 top
NOREF#3476  -  []  196.7 253.03 90 top
NOREF#3477  -  []  231.24 257.85 90 top
NOREF#3478  -  []  209.52 264.23 90 top
NOREF#3479  -  []  283.84 265.58 0 top
NOREF#3480  -  []  288.39 396.29 0 top
NOREF#3481  -  []  134.07 210.89 90 top
NOREF#3482  -  []  199.4 265.9 0 top
NOREF#3483  -  []  228.19 187.71 0 top
NOREF#3484  -  []  237.37 180.3 90 top
NOREF#3485  -  []  164.95 200.42 90 top
NOREF#3486  -  []  237.03 178.07 0 top
NOREF#3487  -  []  162.87 16.49 0 top
NOREF#3488  -  []  239.27 201.77 0 top
NOREF#3489  -  []  157.92 190.01 0 top
NOREF#3490  -  []  183.49 253.03 90 top
NOREF#3491  -  []  235.15 176.17 90 top
NOREF#3492  -  []  196.79 231.3 0 top
NOREF#3493  -  []  201.84 235.2 0 top
NOREF#3494  -  []  210.02 274.45 0 top
NOREF#3495  -  []  139.08 261.22 0 top
NOREF#3496  -  []  191.79 251.93 0 top
NOREF#3497  -  []  221.85 246.47 0 top
NOREF#3498  -  []  225.61 252.78 0 top
NOREF#3499  -  []  233.39 193.03 90 top
NOREF#3500  -  []  147.43 224.11 90 top
NOREF#3501  -  []  151.7 285.06 90 top
NOREF#3502  -  []  180.59 184.98 90 top
NOREF#3503  -  []  203.84 205.58 0 top
NOREF#3504  -  []  236.57 198.18 0 top
NOREF#3505  -  []  164.64 181.15 90 top
NOREF#3506  -  []  208.42 261.77 0 top
NOREF#3507  -  []  271.18 239.15 0 top
NOREF#3508  -  []  183.36 247.38 0 top
NOREF#3509  -  []  125.08 17.15 0 top
NOREF#3510  -  []  244.95 210.32 90 top
NOREF#3511  -  []  234.39 282.02 90 top
NOREF#3512  -  []  192.87 188.11 90 top
NOREF#3513  -  []  186.7 297.01 90 top
NOREF#3514  -  []  159.4 210.55 90 top
NOREF#3515  -  []  274.39 222.02 90 top
NOREF#3516  -  []  243.97 202.09 0 top
NOREF#3517  -  []  213.69 14.59 90 top
NOREF#3518  -  []  149.84 279.54 90 top
NOREF#3519  -  []  251.25 184.35 0 top
NOREF#3520  -  []  195.56 175.77 0 top
NOREF#3521  -  []  236.8 280.49 90 top
NOREF#3522  -  []  131.05 185.49 90 top
NOREF#3523  -  []  231.46 227 0 top
NOREF#3524  -  []  182.03 229.03 90 top
NOREF#3525  -  []  220.83 268.59 90 top
NOREF#3526  -  []  271.11 260.17 90 top
NOREF#3527  -  []  149.72 226.19 0 top
NOREF#3528  -  []  204.32 291.95 90 top
NOREF#3529  -  []  185.42 214.72 90 top
NOREF#3530  -  []  235.05 283.39 0 top
NOREF#3531  -  []  241.44 184.35 0 top
NOREF#3532  -  []  149.84 219.54 90 top
NOREF#3533  -  []  88.14 155.19 0 top
NOREF#3534  -  []  125.25 291.4 90 top
NOREF#3535  -  []  201.75 269.17 0 top
NOREF#3536  -  []  273.6 226.96 0 top
NOREF#3537  -  []  131.22 294.24 90 top
NOREF#3538  -  []  236.84 227.33 0 top
NOREF#3539  -  []  275.17 216.75 0 top
NOREF#3540  -  []  154.39 226.59 90 top
NOREF#3541  -  []  259.39 16.49 0 top
NOREF#3542  -  []  159.22 195.7 90 top
NOREF#3543  -  []  233.6 276.55 0 top
NOREF#3544  -  []  256.55 254.49 90 top
NOREF#3545  -  []  236.7 257.85 90 top
NOREF#3546  -  []  239.4 212 0 top
NOREF#3547  -  []  203.97 205.9 0 top
NOREF#3548  -  []  166.32 212.22 0 top
NOREF#3549  -  []  147.43 284.11 0 top
NOREF#3550  -  []  270.56 197.6 0 top
NOREF#3551  -  []  209.17 231.95 0 top
NOREF#3552  -  []  239.72 223.79 90 top
NOREF#3553  -  []  222.81 246.81 0 top
NOREF#3554  -  []  232.25 222.59 90 top
NOREF#3555  -  []  249.17 231.95 0 top
NOREF#3556  -  []  198.91 232.21 90 top
NOREF#3557  -  []  251.05 232.28 90 top
NOREF#3558  -  []  156.84 227.33 0 top
NOREF#3559  -  []  236.57 242.05 0 top
NOREF#3560  -  []  149.72 281.62 0 top
NOREF#3561  -  []  189.12 196.43 90 top
NOREF#3562  -  []  236.1 220.99 90 top
NOREF#3563  -  []  180.83 265.79 90 top
NOREF#3564  -  []  145.42 286.99 90 top
NOREF#3565  -  []  188.78 184.35 0 top
NOREF#3566  -  []  131.84 21.69 90 top
NOREF#3567  -  []  219.73 238.35 0 top
NOREF#3568  -  []  151.98 226.59 90 top
NOREF#3569  -  []  163.84 207.82 90 top
NOREF#3570  -  []  145.61 197.6 0 top
NOREF#3571  -  []  259.72 273.6 90 top
NOREF#3572  -  []  283.84 267.82 90 top
NOREF#3573  -  []  266.43 222.5 90 top
NOREF#3574  -  []  236.1 216.42 90 top
NOREF#3575  -  []  321.5 18.69 0 top
NOREF#3576  -  []  283.97 210.55 90 top
NOREF#3577  -  []  171.05 289.49 0 top
NOREF#3578  -  []  167.04 299.09 0 top
NOREF#3579  -  []  279.27 261.77 0 top
NOREF#3580  -  []  276.57 245.63 0 top
NOREF#3581  -  []  231.11 260.17 90 top
NOREF#3582  -  []  192.25 218.02 0 top
NOREF#3583  -  []  226.16 193.35 0 top
NOREF#3584  -  []  162.26 236.17 90 top
NOREF#3585  -  []  279.65 212.56 0 top
NOREF#3586  -  []  259.72 213.6 90 top
NOREF#3587  -  []  134.43 292.23 0 top
NOREF#3588  -  []  255.65 184.35 0 top
NOREF#3589  -  []  150.97 190.88 90 top
NOREF#3590  -  []  152.13 214.25 0 top
NOREF#3591  -  []  269.84 224.11 90 top
NOREF#3592  -  []  213.78 267.01 0 top
NOREF#3593  -  []  237.37 251.6 90 top
NOREF#3594  -  []  220.95 261.55 90 top
NOREF#3595  -  []  268.99 180.62 0 top
NOREF#3596  -  []  235.17 212.18 90 top
NOREF#3597  -  []  171.65 233.3 90 top
NOREF#3598  -  []  268.32 198.18 0 top
NOREF#3599  -  []  269.67 190.01 0 top
NOREF#3600  -  []  199.27 260.97 90 top
NOREF#3601  -  []  196.02 192.78 0 top
NOREF#3602  -  []  221.85 292.49 0 top
NOREF#3603  -  []  157.59 175.77 0 top
NOREF#3604  -  []  212.87 227.4 90 top
NOREF#3605  -  []  138.95 264.09 0 top
NOREF#3606  -  []  274.07 196.43 90 top
NOREF#3607  -  []  78.11 0 90 top
NOREF#3608  -  []  206.32 214.76 0 top
NOREF#3609  -  []  142.81 247.68 0 top
NOREF#3610  -  []  196.38 181.15 90 top
NOREF#3611  -  []  146.43 236.47 90 top
NOREF#3612  -  []  142.88 213.02 0 top
NOREF#3613  -  []  154.07 256.43 90 top
NOREF#3614  -  []  191.11 193.35 0 top
NOREF#3615  -  []  204.32 231.95 90 top
NOREF#3616  -  []  147.8 204.99 90 top
NOREF#3617  -  []  197.71 172.86 0 top
NOREF#3618  -  []  236.02 197.6 0 top
NOREF#3619  -  []  244.61 234.89 90 top
NOREF#3620  -  []  147.8 265.39 90 top
NOREF#3621  -  []  267.45 209.24 0 top
NOREF#3622  -  []  237.37 256.43 90 top
NOREF#3623  -  []  239.4 267.5 90 top
NOREF#3624  -  []  140.95 208.91 90 top
NOREF#3625  -  []  246.73 82.65 0 top
NOREF#3626  -  []  209.55 237.49 0 top
NOREF#3627  -  []  196.57 245.63 90 top
NOREF#3628  -  []  275.51 454.29 90 top
NOREF#3629  -  []  283.97 273.09 90 top
NOREF#3630  -  []  146.88 286.59 90 top
NOREF#3631  -  []  197.37 256.43 90 top
NOREF#3632  -  []  152.25 222.59 0 top
NOREF#3633  -  []  180.83 203.76 90 top
NOREF#3634  -  []  209.55 237.49 90 top
NOREF#3635  -  []  256.55 194.49 90 top
NOREF#3636  -  []  197.37 191.6 90 top
NOREF#3637  -  []  152.63 173.69 0 top
NOREF#3638  -  []  223.36 258.18 0 top
NOREF#3639  -  []  193.56 233.37 90 top
NOREF#3640  -  []  168.42 200.97 90 top
NOREF#3641  -  []  243.4 236.38 0 top
NOREF#3642  -  []  239.72 279.22 90 top
NOREF#3643  -  []  191.19 278.07 0 top
NOREF#3644  -  []  277.59 175.77 0 top
NOREF#3645  -  []  221.03 207.69 90 top
NOREF#3646  -  []  274.33 204.33 90 top
NOREF#3647  -  []  162.26 176.17 90 top
NOREF#3648  -  []  138.56 246.51 0 top
